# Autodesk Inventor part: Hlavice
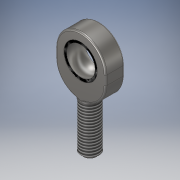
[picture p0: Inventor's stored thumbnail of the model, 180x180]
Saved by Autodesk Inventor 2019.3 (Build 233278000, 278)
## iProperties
Created: 2019-01
Part Number: Hlavice
Material: Ocel, litá
Document SubType Name: Modeling
Designer: B-hon
Density: 7.85 g/cm^3
Appearance: Pololeštěná
Mass: 100.152 g
Surface Area: 50.5554 cm^2
Volume: 12.7583 cm^3
Author: B-hon
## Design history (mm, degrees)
sketch "Náčrt1"
  geometry: L1 (0, 0)-(0, -6); L2 (-16.5, 0)-(-16.5, -6); L3 (16.5, -6)-(16.5, 0); C1 r 9.2 at (0, 0); A1 r 16.5 centre (0, 0) between (16.5, 0) and (-16.5, 0); A2 r 16.5 centre (0, -6) between (-16.5, -6) and (16.5, -6); 2 further points
  constraints: 8 end point, 4 point on circle, 4 tangent, 3 centre point, 1 coincident, 1 midpoint, 1 parallel, 1 vertical
  dimensions: "d0" = 18.4 diameter of C1; "d2" = 33 diameter of A2; "d3" = 6 distance of L3.start L3.end
extrude "Vysunutí1" new body sketch "Náčrt1" distance "d4" = 12.5; taper "d5" = 0 deg
node "Pracovní rovina1"
sketch "Náčrt2"
  geometry: C1 r 6.25 at (0, 6.25); 1 further point
  constraints: 1 centre point
  dimensions: "d6" = 12.5 diameter of C1; "d7" = 6.25 distance of point (0, 0) C1.centre
extrude "Vysunutí2" join sketch "Náčrt2" distance "d8" = 3; taper "d10" = 0 deg; dims "d9" = 1, "d11" = 0, "d21" = 22.2
sketch "Náčrt3"
  geometry: C1 r 6 at (0, 0); 1 further point
  constraints: 1 centre point
  dimensions: "d12" = 12 diameter of C1
extrude "Vysunutí3" join sketch "Náčrt3" distance "d13" = 32; taper "d14" = 0 deg
fillet "Zaoblení1" dims "d15" = 1
chamfer "Zkosení1" distance "d16" = 1.75; stored, may be unused: second distance "d17" = 2, angle "d18" = 45 deg
feature "Závit1" dims "d19" = 10, "d20" = 0
sketch "Náčrt4"
  geometry: C1 r 9.2 at (0, 0) reference; C2 r 11.1 at (0, 0); 1 further point
  constraints: 1 centre point, 1 coincident
  dimensions: "d21" = 22.2 diameter of C2
extrude "Vysunutí4" cut sketch "Náčrt4" distance "d22" = 0.25; taper "d23" = 0 deg
sketch "Náčrt5"
  geometry: C1 r 9.2 at (0, 0) reference; C2 r 11.1 at (0, 0); 1 further point
  constraints: 1 centre point, 1 coincident
  dimensions: "d24" = 22.2 diameter of C2
extrude "Vysunutí5" cut sketch "Náčrt5" distance "d25" = 0.25; taper "d26" = 0 deg
sketch "Náčrt6"
  geometry: L1 (0, 17.717)-(0, -8.374) reference; L2 (7.341, 14.25)-(7.341, -1.75); L3 (7.341, -1.75)-(7.695, -1.75); L4 (7.341, 14.25)-(7.695, 14.25); A1 r 11.1 centre (0, 6.25) between (7.695, -1.75) and (7.695, 14.25); 1 further point
  constraints: 8 end point, 3 vertical, 2 point on circle, 1 centre point, 1 horizontal, 1 perpendicular, 1 point on line, 1 vertical alignment
  dimensions: "d27" = 16 distance of L2.start L2.end; "d28" = 6.25 distance of point (0, 0) A1.centre; "d29" = 11.1 radius of A1
revolve "Rotace1" sketch "Náčrt6" stored, may be unused: angle "d30" = 90 deg
node "Těleso1"
